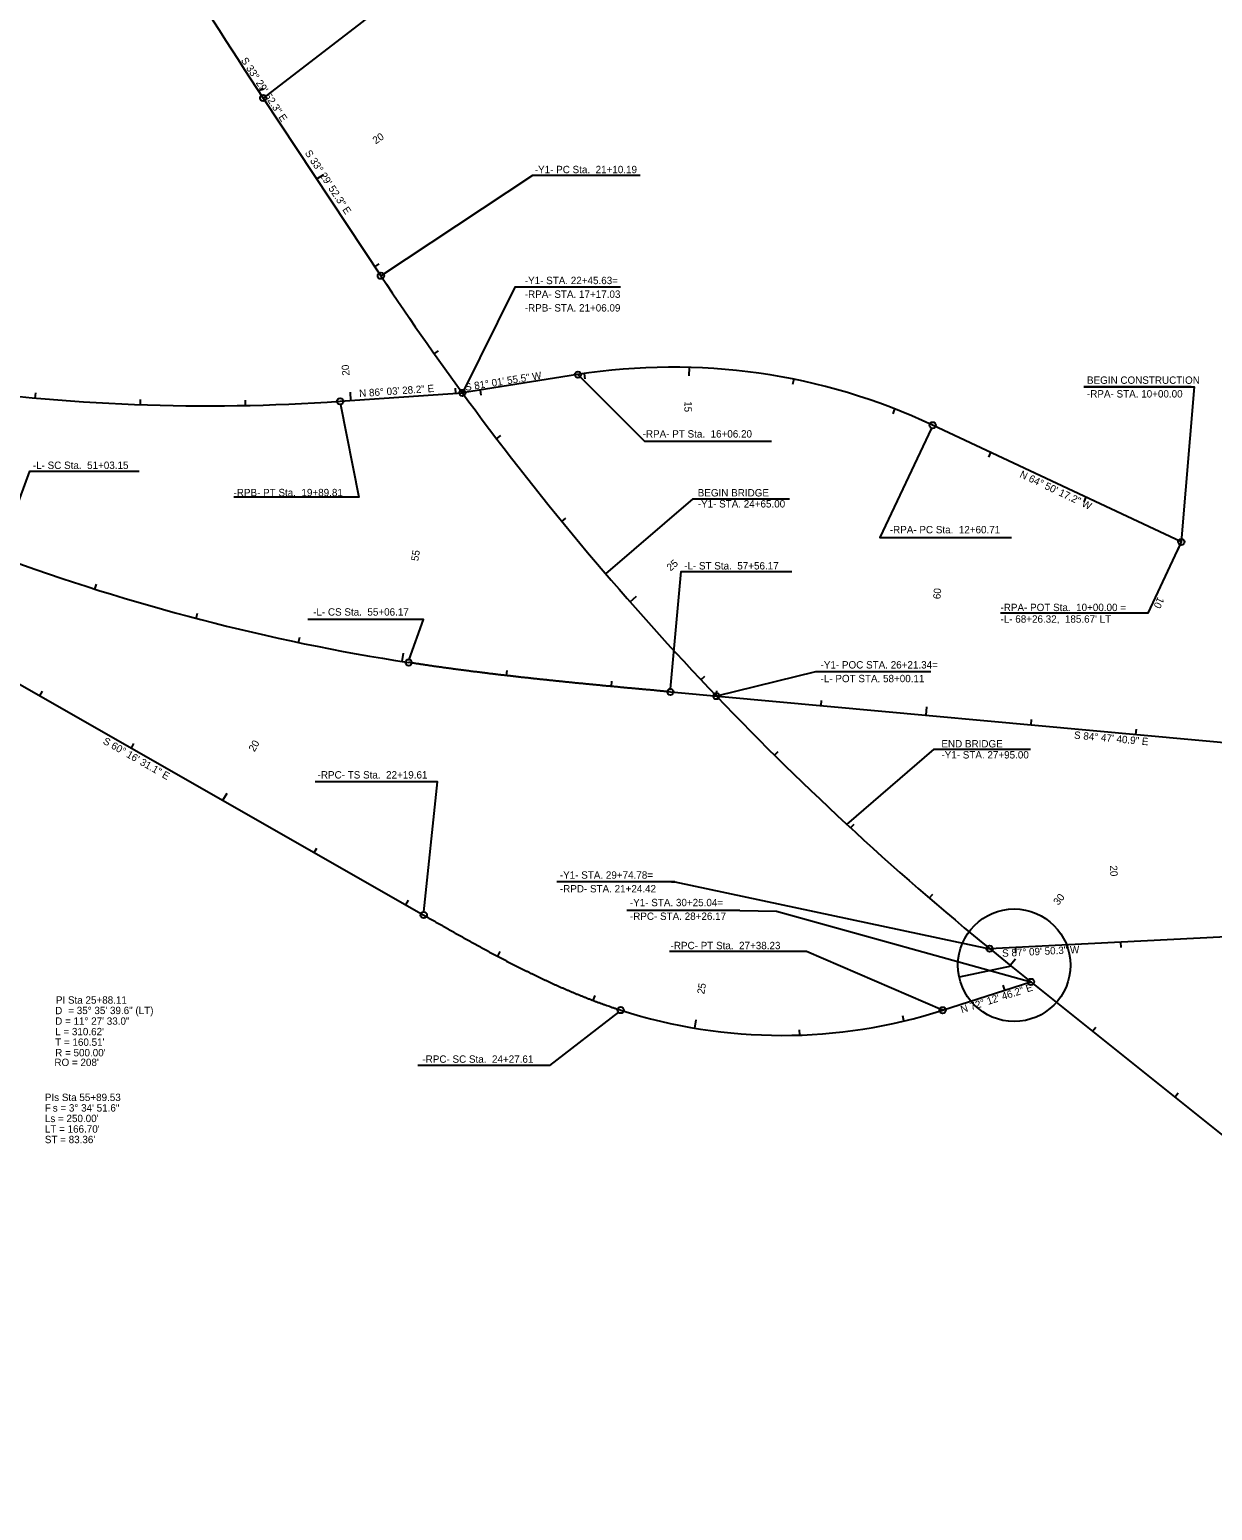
# Model space of a CAD drawing. Extents: x 1636713 to 1642889, y 841520 to 844630.
# Drawn here: x 1640618 to 1641741, y 841624 to 843029 of the extents above; entities that cross this region are included whole.
import ezdxf

# ---------------------------------------------------------------- set-up
doc = ezdxf.new("R2010")
doc.units = 0
for name, color, linetype in [('Exist 4 AWG with gnd feeder circuit in conduit', 7, 'Continuous'), ('Exist 6 AWG with gnd feeder circuit', 7, 'Continuous'), ('Exist 8 AWG with gnd feeder circuit', 7, 'Continuous'), ('Exist 8 AWG with gnd feeder circuit in conduit', 7, 'Continuous'), ('Prop 2 AWG with gnd feeder circuit', 7, 'Continuous'), ('Prop 2 AWG with gnd feeder circuit in conduit', 7, 'Continuous'), ('Prop 4 AWG with gnd feeder circuit', 7, 'Continuous'), ('Prop Cable Guiderail Double Face', 7, 'Continuous'), ('Prop Clearing and Grubbing', 7, 'Continuous')]:
    doc.layers.add(name, color=color, linetype=linetype)

msp = doc.modelspace()

# ---------------------------------------------------------------- linework, layer by layer
at = {"layer": 'Exist 6 AWG with gnd feeder circuit'}
for p, q in [((1641178.9, 842784.9), (1641085.1, 842784.9)), ((1641720.8, 842690.3), (1641618.8, 842690.3)), ((1641473.6, 842420.1), (1641365.9, 842420.1)), ((1641227.3, 842220.6), (1641118.4, 842220.6)), ((1641230.6, 842220.6), (1641121.6, 842220.6)), ((1641292.1, 842193.5), (1641184.9, 842193.5)), ((1641484.8, 842098.8), (1641355.6, 842154.5))]:
    msp.add_line(p, q, dxfattribs=at)
for points in [[(1640966.6, 843199.8), (1641026.4, 843108.2), (1640839.8, 842964.5)], [(1640951.5, 842795.8), (1641095.6, 842891.2), (1641197.7, 842891.2)], [(1641178.9, 842784.9), (1641078.5, 842784.9), (1641028.9, 842684.7)], [(1641138.6, 842702), (1641201.7, 842638.9), (1641322.4, 842638.9)], [(1641618.8, 842690.3), (1641723.5, 842690.3), (1641711.3, 842543.2)], [(1640913.1, 842673.7), (1640930.5, 842585.7), (1640812, 842585.7)], [(1641474.1, 842651.3), (1641425.2, 842547.4), (1641550.2, 842547.4)], [(1640589.5, 842532.7), (1640618.3, 842610.5), (1640722.1, 842610.5)], [(1641165, 842512.9), (1641248, 842584.1), (1641339.4, 842584.1)], [(1641710, 842540.5), (1641679.6, 842475.6), (1641539.6, 842475.6)], [(1641226.5, 842403.9), (1641236.7, 842515.1), (1641341.7, 842515.1)], [(1640978.3, 842431.7), (1640992, 842469.6), (1640882, 842469.6)], [(1641473.6, 842420.1), (1641364.1, 842420.1), (1641270, 842396.9)], [(1641393.7, 842275.2), (1641476.7, 842346.4), (1641568.1, 842346.4)], [(1640992.2, 842192.1), (1641005.4, 842315.5), (1640889.2, 842315.5)], [(1641227.3, 842220.6), (1641230.6, 842220.6), (1641529.4, 842157.2)], [(1641292.1, 842193.5), (1641327.2, 842192.9), (1641568.6, 842125.7)], [(1641355.6, 842154.5), (1641225.6, 842154.5)], [(1641177.1, 842096.8), (1641111.7, 842046.3), (1640986.7, 842046.3)]]:
    msp.add_lwpolyline(points, dxfattribs=at)
for centre in [(1640839.8, 842964.5), (1640951.5, 842795.8), (1641138.6, 842702), (1641028.9, 842684.7), (1640912.9, 842676.7), (1641475.3, 842654), (1641711.3, 842543.2), (1640977.9, 842428.8), (1641226.3, 842400.9), (1641270, 842396.9), (1640992.2, 842189.1), (1641529.4, 842157.2), (1641568.6, 842125.7), (1641179.2, 842098.9), (1641484.8, 842098.8)]:
    msp.add_circle(centre, 3, dxfattribs=at)
at = {"layer": 'Exist 8 AWG with gnd feeder circuit'}
for p, q in [((1640839.8, 842964.5), (1640951.5, 842795.8)), ((1641138.3, 842702), (1641028.9, 842684.7)), ((1640912.9, 842676.7), (1641028.9, 842684.7)), ((1641711.3, 842543.2), (1641475.3, 842654)), ((1640410.5, 842521.2), (1640992.2, 842189.1)), ((1640410.5, 842521.2), (1640992.2, 842189.1)), ((1641226.3, 842400.9), (1642664.1, 842269.9)), ((1642130.1, 842187), (1641529.4, 842157.2)), ((1641549.8, 842140.7), (1642195.1, 841624.1)), ((1641484.8, 842098.8), (1641568.6, 842125.7)), ((1641484.8, 842098.8), (1641568.6, 842125.7))]:
    msp.add_line(p, q, dxfattribs=at)
for centre, radius, start, end in [((1644817.6, 845597.1), 4770, 209.2972, 213.4979), ((1643339.8, 844376.5), 2864, 213.4979, 216.6107), ((1640787.7, 844492.4), 1820, 249.3927, 273.9422), ((1641228.7, 842129.1), 580, 64.8381, 98.9679), ((1643339.8, 844376.5), 2864, 216.6107, 231.3193), ((1641283.4, 844405.3), 2000, 249.6681, 261.2137), ((1641332.1, 842574.9), 500, 252.1928, 287.7872), ((1641332.1, 842574.9), 500, 252.1928, 287.7872)]:
    msp.add_arc(centre, radius, start, end, dxfattribs=at)
for points in [[(1641226.3, 842400.9), (1641222.9, 842401.2), (1641219.5, 842401.5), (1641216.2, 842401.8), (1641212.8, 842402.1), (1641209.4, 842402.5), (1641206.1, 842402.8), (1641202.7, 842403.1), (1641199.3, 842403.4), (1641196, 842403.7), (1641192.6, 842404), (1641189.2, 842404.3), (1641185.9, 842404.6), (1641182.5, 842404.9), (1641179.2, 842405.2), (1641175.8, 842405.6), (1641172.4, 842405.9), (1641169.1, 842406.2), (1641165.7, 842406.5), (1641162.3, 842406.8), (1641159, 842407.2), (1641155.6, 842407.5), (1641152.3, 842407.8), (1641148.9, 842408.1), (1641145.5, 842408.5), (1641142.2, 842408.8), (1641138.8, 842409.1), (1641135.4, 842409.4), (1641132.1, 842409.8), (1641128.7, 842410.1), (1641125.4, 842410.5), (1641122, 842410.8), (1641118.6, 842411.1), (1641115.3, 842411.5), (1641111.9, 842411.8), (1641108.6, 842412.2), (1641105.2, 842412.6), (1641101.8, 842412.9), (1641098.5, 842413.3), (1641095.1, 842413.6), (1641091.8, 842414), (1641088.4, 842414.4), (1641085, 842414.7), (1641081.7, 842415.1), (1641078.3, 842415.5), (1641075, 842415.9), (1641071.6, 842416.3), (1641068.3, 842416.7), (1641064.9, 842417), (1641061.5, 842417.4), (1641058.2, 842417.8), (1641054.8, 842418.2), (1641051.5, 842418.7), (1641048.1, 842419.1), (1641044.8, 842419.5), (1641041.4, 842419.9), (1641038.1, 842420.3), (1641034.7, 842420.8), (1641031.4, 842421.2), (1641028, 842421.6), (1641024.7, 842422.1), (1641021.3, 842422.5), (1641018, 842423), (1641014.6, 842423.4), (1641011.3, 842423.9), (1641007.9, 842424.4), (1641004.6, 842424.8), (1641001.2, 842425.3), (1640997.9, 842425.8), (1640994.6, 842426.3), (1640991.2, 842426.8), (1640987.9, 842427.3), (1640984.5, 842427.8), (1640981.2, 842428.3), (1640977.9, 842428.8)], [(1640992.2, 842189.1), (1640994.7, 842187.7), (1640997.1, 842186.3), (1640999.5, 842184.9), (1641002, 842183.5), (1641004.4, 842182.1), (1641006.9, 842180.7), (1641009.3, 842179.4), (1641011.8, 842178), (1641014.2, 842176.6), (1641016.6, 842175.2), (1641019.1, 842173.8), (1641021.5, 842172.4), (1641024, 842171.1), (1641026.4, 842169.7), (1641028.9, 842168.3), (1641031.3, 842166.9), (1641033.8, 842165.6), (1641036.3, 842164.2), (1641038.7, 842162.8), (1641041.2, 842161.5), (1641043.6, 842160.1), (1641046.1, 842158.8), (1641048.6, 842157.4), (1641051, 842156.1), (1641053.5, 842154.7), (1641056, 842153.4), (1641058.5, 842152.1), (1641060.9, 842150.8), (1641063.4, 842149.4), (1641065.9, 842148.1), (1641068.4, 842146.8), (1641070.9, 842145.5), (1641073.4, 842144.2), (1641075.9, 842142.9), (1641078.4, 842141.7), (1641080.9, 842140.4), (1641083.4, 842139.1), (1641085.9, 842137.9), (1641088.4, 842136.6), (1641090.9, 842135.4), (1641093.5, 842134.1), (1641096, 842132.9), (1641098.5, 842131.7), (1641101.1, 842130.4), (1641103.6, 842129.2), (1641106.1, 842128), (1641108.7, 842126.9), (1641111.2, 842125.7), (1641113.8, 842124.5), (1641116.4, 842123.3), (1641118.9, 842122.2), (1641121.5, 842121), (1641124.1, 842119.9), (1641126.6, 842118.8), (1641129.2, 842117.7), (1641131.8, 842116.6), (1641134.4, 842115.5), (1641137, 842114.4), (1641139.6, 842113.4), (1641142.2, 842112.3), (1641144.8, 842111.3), (1641147.4, 842110.2), (1641150.1, 842109.2), (1641152.7, 842108.2), (1641155.3, 842107.2), (1641157.9, 842106.2), (1641160.6, 842105.3), (1641163.2, 842104.3), (1641165.9, 842103.4), (1641168.5, 842102.5), (1641171.2, 842101.5), (1641173.9, 842100.6), (1641176.5, 842099.8), (1641179.2, 842098.9)], [(1640992.2, 842189.1), (1640994.7, 842187.7), (1640997.1, 842186.3), (1640999.5, 842184.9), (1641002, 842183.5), (1641004.4, 842182.1), (1641006.9, 842180.7), (1641009.3, 842179.4), (1641011.8, 842178), (1641014.2, 842176.6), (1641016.6, 842175.2), (1641019.1, 842173.8), (1641021.5, 842172.4), (1641024, 842171.1), (1641026.4, 842169.7), (1641028.9, 842168.3), (1641031.3, 842166.9), (1641033.8, 842165.6), (1641036.3, 842164.2), (1641038.7, 842162.8), (1641041.2, 842161.5), (1641043.6, 842160.1), (1641046.1, 842158.8), (1641048.6, 842157.4), (1641051, 842156.1), (1641053.5, 842154.7), (1641056, 842153.4), (1641058.5, 842152.1), (1641060.9, 842150.8), (1641063.4, 842149.4), (1641065.9, 842148.1), (1641068.4, 842146.8), (1641070.9, 842145.5), (1641073.4, 842144.2), (1641075.9, 842142.9), (1641078.4, 842141.7), (1641080.9, 842140.4), (1641083.4, 842139.1), (1641085.9, 842137.9), (1641088.4, 842136.6), (1641090.9, 842135.4), (1641093.5, 842134.1), (1641096, 842132.9), (1641098.5, 842131.7), (1641101.1, 842130.4), (1641103.6, 842129.2), (1641106.1, 842128), (1641108.7, 842126.9), (1641111.2, 842125.7), (1641113.8, 842124.5), (1641116.4, 842123.3), (1641118.9, 842122.2), (1641121.5, 842121), (1641124.1, 842119.9), (1641126.6, 842118.8), (1641129.2, 842117.7), (1641131.8, 842116.6), (1641134.4, 842115.5), (1641137, 842114.4), (1641139.6, 842113.4), (1641142.2, 842112.3), (1641144.8, 842111.3), (1641147.4, 842110.2), (1641150.1, 842109.2), (1641152.7, 842108.2), (1641155.3, 842107.2), (1641157.9, 842106.2), (1641160.6, 842105.3), (1641163.2, 842104.3), (1641165.9, 842103.4), (1641168.5, 842102.5), (1641171.2, 842101.5), (1641173.9, 842100.6), (1641176.5, 842099.8), (1641179.2, 842098.9)]]:
    msp.add_spline(points, degree=3, dxfattribs=at)
at = {"layer": 'Prop 2 AWG with gnd feeder circuit in conduit'}
for p, q in [((1640890.7, 842887.7), (1640897.3, 842892.1)), ((1641244.2, 842708.9), (1641243.9, 842700.9)), ((1640923, 842677.4), (1640922.5, 842685.4)), ((1641711.3, 842543.2), (1641707.9, 842535.9)), ((1641188, 842486.4), (1641194, 842491.7)), ((1640971.8, 842429.7), (1640973, 842437.6)), ((1641469.1, 842378.8), (1641469.8, 842386.8)), ((1640801.5, 842298), (1640805.5, 842304.9)), ((1641653.7, 842163.4), (1641653.9, 842158.4)), ((1641549, 842141.4), (1641554, 842147.6)), ((1641249.5, 842081.8), (1641250.8, 842089.7))]:
    msp.add_line(p, q, dxfattribs=at)
at = {"layer": 'Prop 4 AWG with gnd feeder circuit'}
for p, q in [((1640835.5, 842971.1), (1640839.6, 842973.9)), ((1640945.8, 842804.3), (1640950, 842807.1)), ((1641002.2, 842721.7), (1641006.3, 842724.6)), ((1641144.5, 842702.9), (1641145.2, 842698)), ((1641343.4, 842697.6), (1641342.4, 842692.7)), ((1640623.4, 842679.8), (1640623.8, 842684.8)), ((1641022.8, 842684.3), (1641022.4, 842689.3)), ((1641045.7, 842687.3), (1641046.5, 842682.4)), ((1640723.2, 842673.5), (1640723.3, 842678.5)), ((1640823.1, 842672.7), (1640823, 842677.7)), ((1641439.2, 842669.5), (1641437.4, 842664.9)), ((1641061.4, 842641.1), (1641065.4, 842644.2)), ((1641530.3, 842628.2), (1641528.2, 842623.7)), ((1641620.8, 842585.7), (1641618.7, 842581.2)), ((1641123.4, 842562.6), (1641127.2, 842565.8)), ((1640680, 842498.5), (1640681.5, 842503.2)), ((1640776.1, 842470.7), (1640777.4, 842475.5)), ((1640873.4, 842447.8), (1640874.4, 842452.7)), ((1641070.9, 842416.4), (1641071.4, 842421.3)), ((1641255.3, 842412.4), (1641259, 842415.8)), ((1640627.8, 842397.2), (1640630.3, 842401.5)), ((1641170.3, 842406.1), (1641170.8, 842411.1)), ((1641269.9, 842396.9), (1641270.4, 842401.9)), ((1641369.5, 842387.9), (1641369.9, 842392.9)), ((1641568.7, 842369.7), (1641569.1, 842374.7)), ((1641668.3, 842360.7), (1641668.7, 842365.6)), ((1640714.7, 842347.6), (1640717.1, 842351.9)), ((1641325.2, 842340.8), (1641328.7, 842344.4)), ((1641397.4, 842271.8), (1641400.8, 842275.4)), ((1640888.3, 842248.4), (1640890.8, 842252.7)), ((1640975.2, 842198.8), (1640977.7, 842203.2)), ((1641472.1, 842205.2), (1641475.4, 842209)), ((1641062.4, 842150), (1641064.8, 842154.4)), ((1641553.8, 842158.4), (1641554.1, 842153.4)), ((1641543.7, 842117.7), (1641542.1, 842122.5)), ((1641153.1, 842108), (1641154.9, 842112.7)), ((1641448, 842088.6), (1641446.9, 842093.4)), ((1641349.1, 842075.2), (1641348.9, 842080.2)), ((1641627.1, 842078.9), (1641630.2, 842082.8)), ((1641705.2, 842016.4), (1641708.3, 842020.3))]:
    msp.add_line(p, q, dxfattribs=at)
at = {"layer": 'Prop Cable Guiderail Double Face'}
msp.add_line((1642130.1, 842187), (1641529.4, 842157.2), dxfattribs=at)
at = {"layer": 'Prop Clearing and Grubbing'}
msp.add_line((1641549.8, 842140.7), (1641500.5, 842130.1), dxfattribs=at)
msp.add_circle((1641552.7, 842141.5), 53.4, dxfattribs=at)

# ---------------------------------------------------------------- texts
at = {"layer": 'Exist 4 AWG with gnd feeder circuit in conduit'}
for s, rotation, p in [('20', 33.4979, (1640946.5, 842920.5)), ('20', 93.9422, (1640921.8, 842701.3)), ('15', 268.4767, (1641239.8, 842676.9)), ('55', 81.037, (1640987, 842524.7)), ('25', 41.2963, (1641226.5, 842515.1)), ('60', 84.7947, (1641482.6, 842488.7)), ('10', 244.8381, (1641689.2, 842491.6)), ('20', 60.2753, (1640831.5, 842343.5)), ('20', 272.836, (1641643.5, 842236.1)), ('30', 51.299, (1641594.6, 842197.8)), ('25', 80.4885, (1641258.5, 842113.7))]:
    msp.add_text(s, height=7, rotation=rotation, dxfattribs=at).set_placement(p)
at = {"layer": 'Exist 6 AWG with gnd feeder circuit'}
for s, p in [('-Y1- PC Sta.  21+10.19', (1641097.6, 842893.2)), ('-L- SC Sta.  51+03.15', (1640621.1, 842612.5)), ('-RPB- PT Sta.  19+89.81', (1640811.6, 842586.6)), ('-Y1- STA. 24+65.00', (1641252.3, 842575.9)), ('BEGIN BRIDGE', (1641252.3, 842586.4)), ('-RPA- PC Sta.  12+60.71', (1641434.6, 842551.4)), ('-Y1- STA. 27+95.00', (1641483.6, 842337.7)), ('END BRIDGE', (1641483.6, 842348.2)), ('-RPC- TS Sta.  22+19.61', (1640891.4, 842318.7)), ('-RPC- PT Sta.  27+38.23', (1641226.5, 842156.7)), ('-RPC- SC Sta.  24+27.61', (1640990.9, 842048.9))]:
    msp.add_text(s, height=7, rotation=360, dxfattribs=at).set_placement(p)
for s, p in [('-Y1- STA. 22+45.63=', (1641088.1, 842787.9)), ('-RPA- STA. 17+17.03', (1641088.1, 842774.9)), ('-RPB- STA. 21+06.09', (1641088.1, 842761.9)), ('BEGIN CONSTRUCTION', (1641621.8, 842693.3)), ('-RPA- STA. 10+00.00', (1641621.8, 842680.3)), ('-RPA- PT Sta.  16+06.20', (1641200, 842642.3)), ('-L- ST Sta.  57+56.17', (1641239.4, 842517.1)), ('-RPA- POT Sta.  10+00.00 =', (1641539.7, 842477.6)), ('-L- CS Sta.  55+06.17', (1640887.2, 842473.3)), ("-L- 68+26.32,  185.67' LT", (1641539.7, 842466.6)), ('-Y1- POC STA. 26+21.34=', (1641368.9, 842423.1)), ('-L- POT STA. 58+00.11', (1641368.9, 842410.1)), ('-Y1- STA. 29+74.78=', (1641121.4, 842223.6)), ('-RPD- STA. 21+24.42', (1641121.4, 842210.6)), ('-Y1- STA. 30+25.04=', (1641187.9, 842197.5)), ('-RPC- STA. 28+26.17', (1641187.9, 842184.5))]:
    msp.add_text(s, height=7, dxfattribs=at).set_placement(p)
at = {"layer": 'Exist 8 AWG with gnd feeder circuit in conduit'}
for s, rotation, p in [('S 33%%d 29\' 52.3" E', 303.4979, (1640818.3, 843000.3)), ('S 33%%d 29\' 52.3" E', 303.4979, (1640879, 842912.4)), ('S 81%%d 01\' 55.5" W', 8.9679, (1641031.9, 842686.6)), ('N 86%%d 03\' 28.2" E', 3.9422, (1640931.1, 842680.7)), ('N 64%%d 50\' 17.2" W', 334.8381, (1641557.3, 842605)), ('S 60%%d 16\' 31.1" E', 330.2753, (1640687, 842352.2)), ('S 84%%d 47\' 40.9" E', 354.7947, (1641609.3, 842356.6)), ('S 87%%d 09\' 50.3" W', 2.836, (1641541.4, 842149.4)), ('N 72%%d 12\' 46.2" E', 17.7872, (1641503.1, 842095.8))]:
    msp.add_text(s, height=7, rotation=rotation, dxfattribs=at).set_placement(p)
at = {"layer": 'Prop 2 AWG with gnd feeder circuit'}
for s, p in [('PI Sta 25+88.11', (1640643, 842105)), ('D', (1640642.3, 842095)), ('D = 11%%d 27\' 33.0"', (1640642.3, 842085)), ('= 35%%d 35\' 39.6" (LT)', (1640654.7, 842095.1)), ("L = 310.62'", (1640642.3, 842075)), ("T = 160.51'", (1640642.3, 842065)), ("R = 500.00'", (1640642.3, 842055)), ("RO = 208'", (1640641.6, 842045.8)), ('PIs Sta 55+89.53', (1640632.5, 842012.6)), ('F', (1640632.5, 842002.6)), ('s = 3%%d 34\' 51.6"', (1640640, 842002.6)), ("Ls = 250.00'", (1640632.5, 841992.6)), ("ST = 83.36'", (1640632.5, 841972.6)), ("LT = 166.70'", (1640632.5, 841982.6))]:
    msp.add_text(s, height=7, dxfattribs=at).set_placement(p)

doc.saveas('drawing.dxf')
